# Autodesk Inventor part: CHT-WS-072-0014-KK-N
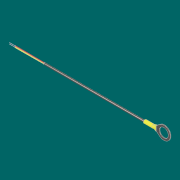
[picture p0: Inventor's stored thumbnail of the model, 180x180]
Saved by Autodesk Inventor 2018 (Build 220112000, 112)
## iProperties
Created: 2017-05
Part Number: CHT-WS-072-0014-KK-N
Material: Generic
Document SubType Name: Modeling
Designer: JN
Density: 1 g/cm^3
Appearance: Steel - Polished
Author: JN
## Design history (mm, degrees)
sketch "Sketch1"
  geometry: L1 (-5.054, 7.651)-(-10.033, 3.471); L2 (-10.033, 3.471)-(-10.033, -3.536); L3 (-10.033, -3.536)-(-5.054, -7.716); L4 (-10.033, -0.032)-(11.43, -0.032); L5 (5.836, 8.965)-(5.836, -9.03); C1 r 6.985 at (1.397, -0.032); A1 r 10.033 centre (1.397, -0.032) between (-5.054, -7.716) and (-5.054, 7.651)
  constraints: 10 end point, 5 point on circle, 2 centre point, 2 tangent, 2 vertical, 1 coincident, 1 midpoint, 1 other
  dimensions: "d0" = 13.97 diameter of C1; "d1" = 20.066 diameter of A1; "d66" = 4.445 distance edge to line of C1 L2
extrude "Extrusion1" new body sketch "Sketch1" stored distance "d7" = 1.0668; taper "d8" = 0 deg
sketch "Sketch3"
  geometry: L1 (0, 0)-(-1.067, 0) reference; L2 (0, 7.007)-(0, 0) reference; L3 (0, 7.007)-(-1.067, 7.007) reference; L4 (-1.067, 0)-(-1.067, 7.007) reference; L5 (0.317, 7.324)-(-1.702, 7.324); L6 (-1.702, 7.324)-(-1.702, -0.318); L7 (-1.702, -0.318)-(0.317, -0.318); L8 (0.317, -0.318)-(0.317, 7.324); L9 (-0.692, 7.324)-(-0.692, -0.318); L10 (0.317, 3.503)-(-1.702, 3.503); 1 further point
  constraints: 12 end point, 6 parallel, 5 midpoint, 1 horizontal, 1 perpendicular
  dimensions: "d15" = 0.3175 distance between parallel lines of L2 L8; "d16" = 0.635 distance between parallel lines of L4 L6; "d17" = 0.3175 distance between parallel lines of L3 L5; "d18" = 0.3175 distance between parallel lines of L1 L7
  node "Projected Loop1"
workplane "Work Plane1"
sketch "Sketch4"
  geometry: L1 (0.317, -0.318)-(0.317, 7.324) reference; L2 (0.317, 7.324)-(-1.702, 7.324) reference; L3 (-1.702, 7.324)-(-1.702, -0.318) reference; L4 (-1.702, -0.318)-(0.317, -0.318) reference; L5 (0.317, 3.503)-(-1.702, 3.503); L6 (-0.692, 7.324)-(-0.692, -0.318); L7 (-2.337, 5.439)-(-2.337, 1.568); A1 r 2.54 centre (-0.692, 3.503) between (-2.337, 1.568) and (-2.337, 5.439); 2 further points
  constraints: 6 end point, 5 midpoint, 2 point on circle, 1 centre point, 1 coincident, 1 point on line, 1 vertical
  dimensions: "d37" = 5.08 diameter of A1; "d38" = 0.635 distance between parallel lines of L3 L7
sketch "3D Sketch1"
loft "Loft1" sketch "Sketch4", "3D Sketch1" dims "d21" = 0, "d22" = 90 deg, "d25" = 0, "d26" = 90 deg, "d39" = 0, "d40" = 90 deg
sketch "Sketch5"
  geometry: L1 (-1.645, 1.936)-(-1.645, -1.936) reference; A1 r 2.54 centre (0, 0) between (0.07, -2.539) and (0.857, 2.391) reference; A2 r 2.54 centre (0, 0) between (0.857, 2.391) and (-1.645, 1.936) reference; A3 r 2.54 centre (0, 0) between (0.857, 2.391) and (-1.645, 1.936) reference; A4 r 2.54 centre (0, 0) between (-1.645, -1.936) and (0.07, -2.539) reference; A5 r 2.54 centre (0, 0) between (0.07, -2.539) and (0.857, 2.391) reference
extrude "Extrusion3" new body sketch "Sketch5" distance "d27" = 12.7; taper "d28" = 0 deg
sketch "Sketch6" dims "d29" = 1.27, "d30" = 1.778
  geometry: L1 (0, 3.446)-(2.019, 3.446); L2 (2.54, 0)-(-1.645, 0); L3 (-1.645, 1.936)-(-1.645, -1.936) reference; A1 r 2.54 centre (0, 0) between (0.07, -2.539) and (0.857, 2.391) reference; 2 further points; 1 other entity
  constraints: 4 end point, 2 midpoint, 1 point on circle, 2 other
extrude "Extrusion4" cut sketch "Sketch6" stored distance "d32" = 12.7; taper "d33" = 0 deg
extrude "Extrusion5" new body sketch "Sketch6" distance "d34" = 152.4; taper "d35" = 0 deg
workplane "Work Plane2"
sketch "Sketch8"
  geometry: C1 r 0.635 at (0.187, 0.635) reference; C2 r 0.635 at (0.187, -0.635) reference; C3 r 0.635 at (0.187, 0.952); C4 r 0.635 at (0.187, -0.953)
  constraints: 2 centre point
  dimensions: "d43" = 1.27 diameter of C3; "d45" = 0.3175 distance of C1.centre C3.centre; "d46" = 1.27 diameter of C4; "d47" = 0.3175 distance of C2.centre C4.centre
sketch "3D Sketch2"
loft "Loft2" dims "d48" = 0, "d49" = 90 deg, "d50" = 0, "d51" = 90 deg, "d52" = 0, "d53" = 90 deg
loft "Loft3" dims "d54" = 0, "d55" = 90 deg, "d56" = 0, "d57" = 90 deg, "d58" = 0, "d59" = 90 deg
sketch "Sketch9"
  geometry: C1 r 0.381 at (0, 0)
  constraints: 1 centre point
  dimensions: "d60" = 0.762 diameter of C1
sketch "Sketch10"
  geometry: C1 r 0.381 at (0, 0)
  constraints: 1 centre point
  dimensions: "d61" = 0.762 diameter of C1
extrude "Extrusion6" join sketch "Sketch9" distance "d62" = 8.46667; taper "d63" = 0 deg
extrude "Extrusion7" join sketch "Sketch10" distance "d64" = 8.46667; taper "d65" = 0 deg
body "Solid1"
sketch "Sketch7"
  geometry: L1 (1.01, 1.395)-(1.01, -1.395) reference; L2 (-1.048, 0)-(1.492, 0); C1 r 0.635 at (0.187, 0.635); C2 r 0.635 at (0.187, -0.635); 3 further points; 3 other entities
  constraints: 4 end point, 2 centre point, 2 tangent, 2 vertical, 1 horizontal, 8 other
  dimensions: "d41" = 1.27 diameter of C1
body "Solid2"
body "Solid3"
body "Solid4"
node "Projected Loop5"
other parameters: "d3" = 14.986 (derived), "d5" = 10.49782 (derived), "d19" = 5.08, "d42" = 44.45
